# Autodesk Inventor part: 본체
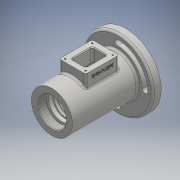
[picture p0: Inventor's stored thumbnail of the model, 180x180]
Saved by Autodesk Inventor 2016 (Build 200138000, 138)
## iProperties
Created: 2017-05
Part Number: 본체
Material: 일반
Document SubType Name: Modeling
Designer: USER
Density: 1 g/cm^3
Appearance: 기본값
Author: USER
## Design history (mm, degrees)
sketch "스케치1"
  geometry: C1 r 53 at (0, 0); 1 further point
  constraints: 1 centre point, 1 coincident
  dimensions: "d0" = 106 diameter of C1
extrude "돌출1" new body sketch "스케치1" distance "d1" = 13; taper "d2" = 0 deg
sketch "스케치2"
  geometry: C1 r 31 at (0, 0); 1 further point
  constraints: 1 centre point, 1 coincident
  dimensions: "d3" = 62 diameter of C1
extrude "돌출2" join sketch "스케치2" distance "d4" = 3; taper "d5" = 0 deg
sketch "스케치3"
  geometry: C1 r 31 at (0, 0); 1 further point
  constraints: 1 centre point, 1 coincident
  dimensions: "d6" = 62 diameter of C1
extrude "돌출3" join sketch "스케치3" distance "d7" = 99; taper "d8" = 0 deg
sketch "스케치4"
  geometry: L1 (-138.323, 0)-(35.373, 0); L2 (-99, 31)-(-99, -31) reference; L3 (-99, 0)-(-99, 21); L4 (-99, 21)-(-87, 21); L5 (-87, 21)-(-87, 24); L6 (-87, 24)-(-84, 24); L7 (-84, 24)-(-84, 20); L8 (-84, 20)-(-78, 20); L9 (-78, 20)-(-78, 17.5); L10 (-78, 17.5)-(-74.75, 17.5); L11 (-74.75, 17.5)-(-74.75, 18.5); L12 (-74.75, 18.5)-(-73, 18.5); L13 (-73, 18.5)-(-73, 17.5); L14 (-73, 17.5)-(-62, 17.5); L15 (-62, 17.5)-(-62, 26); L16 (-62, 26)-(-24, 26); L17 (-24, 26)-(-24, 17.5); L18 (-24, 17.5)-(-13, 17.5); L19 (-13, 17.5)-(-13, 16.5); L20 (-13, 16.5)-(-11, 16.5); L21 (-8, 13.5)-(-8, 10); L22 (-8, 10)-(-5.3, 10); L23 (-5.3, 10)-(-5.3, 12.5); L24 (-5.3, 12.5)-(2, 12.5); L25 (2, 12.5)-(2, 16); L26 (2, 16)-(16, 22); L27 (16, -31)-(16, 31) reference; L28 (0, 31)-(-99, 31) reference; L29 (16, 22)-(16, 0); L30 (-99, 0)-(16, 0); A1 r 3 centre (-11, 13.5) between (-8, 13.5) and (-11, 16.5); 1 further point
  constraints: 54 end point, 16 perpendicular, 4 horizontal, 3 vertical, 2 midpoint, 2 point on circle, 2 point on line, 2 tangent, 1 centre point, 1 collinear, 1 horizontal alignment
  dimensions: "d9" = 42 diameter of L4 L1; "d10" = 48 diameter of L6 L1; "d11" = 3 distance of L5.end L6.end; "d12" = 40 diameter of L8 L1; "d13" = 12 distance of L3.end L4.end; "d14" = 21 distance between parallel lines of L2 L9; "d15" = 35 diameter of L10 L1; "d16" = 37 diameter of L12 L1; "d17" = 1.75 distance of L11.end L12.end; "d18" = 26 distance between parallel lines of L3 L13; "d19" = 11 distance of L13.end L14.end; "d20" = 35 diameter of L14 L1; "d21" = 38 distance of L15.end L16.end; "d22" = 52 diameter of L16 L1; "d23" = 11 distance of L17.end L18.end; "d24" = 35 diameter of L18 L1; "d25" = 3 radius of A1; "d26" = 33 diameter of L20 L1; "d27" = 2.7 distance of L21.end L22.end; "d28" = 20 diameter of L22 L1; "d29" = 25 diameter of L24 L1; "d30" = 7.3 distance of L23.end L24.end; "d31" = 32 diameter of L25.end L1; "d32" = 44 diameter of L26.end L1; "d33" = 14 distance from line of L25 L26.end
revolve "회전1" sketch "스케치4" stored, may be unused: angle "d34" = 90 deg
fillet "모깎기2" dims "d36" = 0.3
chamfer "모따기1" distance "d37" = 1; stored, may be unused: second distance "d38" = 2, angle "d39" = 45 deg
fillet "모깎기3" dims "d43" = 0.3
chamfer "모따기4" distance "d47" = 0.7; stored, may be unused: second distance "d48" = 2, angle "d49" = 30 deg
fillet "모깎기4" dims "d50" = 3
sketch "스케치8"
  geometry: A1 r 41.5 centre (0, 0) between (0, 41.5) and (-41.5, 0); A2 r 45.5 centre (0, 0) between (0, 45.5) and (-45.5, 0); A3 r 37.5 centre (0, 0) between (0, 37.5) and (-37.5, 0); A4 r 4 centre (0, 41.5) between (0, 37.5) and (0, 45.5); A5 r 4 centre (-41.5, 0) between (-45.5, 0) and (-37.5, 0); A6 r 41.5 centre (0, 0) between (0, -41.5) and (41.5, 0); A7 r 45.5 centre (0, 0) between (0, -45.5) and (45.5, 0); A8 r 37.5 centre (0, 0) between (0, -37.5) and (37.5, 0); A9 r 4 centre (0, -41.5) between (0, -37.5) and (0, -45.5); A10 r 4 centre (41.5, 0) between (45.5, 0) and (37.5, 0); 1 further point
  constraints: 20 point on circle, 10 centre point, 8 tangent, 2 coincident, 2 horizontal alignment, 2 vertical alignment
  dimensions: "d51" = 45.5 radius of A2; "d53" = 41.5 radius of A1; "d54" = 45.5 radius of A7; "d55" = 41.5 radius of A6
extrude "돌출4" cut sketch "스케치8" stored distance "d56" = 99; taper "d57" = 0 deg
node "작업 평면1"
sketch "스케치9"
  geometry: L1 (-20, -18)-(20, -18); L2 (20, -18)-(20, -68); L3 (20, -68)-(-20, -68); L4 (-20, -68)-(-20, -18); L5 (-20, -43)-(0, -43); L6 (-31, -99)-(31, -99) reference; 2 further points
  constraints: 10 end point, 2 horizontal, 2 midpoint, 2 parallel, 1 perpendicular, 1 vertical alignment
  dimensions: "d59" = 50 distance of L1.end L2.end; "d60" = 40 distance of L1.start L1.end; "d61" = 56 distance between parallel lines of L6 L5
extrude "돌출5" join sketch "스케치9" stored distance "d62" = 99; taper "d63" = 0 deg
sketch "스케치10"
  geometry: L1 (-20, -18)-(20, -18) reference; L2 (-20, -68)-(-20, -18) reference; L3 (20, -68)-(-20, -68) reference; L4 (20, -18)-(20, -68) reference; L5 (-11, -27)-(11, -27); L6 (11, -27)-(11, -59); L7 (11, -59)-(-11, -59); L8 (-11, -59)-(-11, -27); 4 further points
  constraints: 8 end point, 3 midpoint, 2 parallel, 1 horizontal, 1 horizontal alignment, 1 perpendicular, 1 vertical alignment
  dimensions: "d64" = 32 distance of L5.end L6.end; "d65" = 22 distance of L6.end L7.end
extrude "돌출6" cut sketch "스케치10" stored distance "d66" = 99; taper "d67" = 0 deg
fillet "모깎기5" dims "d68" = 3
fillet "모깎기6" dims "d69" = 3
fillet "모깎기7" dims "d73" = 3
chamfer "모따기6" distance "d74" = 1; stored, may be unused: second distance "d75" = 2, angle "d76" = 30 deg
fillet "모깎기8" dims "d77" = 3
feature "스레드1" dims "d78" = 10, "d79" = 0
sketch "스케치11"
  geometry: L1 (-20, -65)-(-20, -21) reference; L2 (-20, -65)-(-20, -21) reference; L3 (-20, -43)-(20, -43); L4 (20, -21)-(20, -65) reference; L5 (17, -68)-(-17, -68) reference; L6 (0, -68)-(0, -18); L7 (17, -18)-(-17, -18) reference; 5 further points
  constraints: 4 end point, 4 midpoint, 2 horizontal alignment, 2 vertical alignment
  dimensions: "d80" = 41 distance of point (15.5, -63.5) point (15.5, -22.5); "d81" = 31 distance of point (15.5, -63.5) point (-15.5, -63.5); "d82" = 15.5 distance from line of point (-15.5, -63.5) L6; "d83" = 20.5 distance from line of point (-15.5, -22.5) L3
hole "구멍1" sketch "스케치11" at (-15.5, -22.5), (15.5, -22.5), (15.5, -63.5), (-15.5, -63.5) diameter "d84" = 2.459; stored, may be unused: countersink angle "d88" = 90 deg, drill point angle "d90" = 118 deg; dims "d85" = 6, "d86" = 4, "d87" = 2, "d89" = 8
sketch "스케치12"
  geometry: L1 (13, -34)-(75, -34) reference; L2 (0, 44)-(0, 0) reference; 2 further points
  constraints: 1 other
  dimensions: "d91" = 56 distance from line of L1 point (8, 22); "d92" = 8 distance from line of L2 point (8, 22)
feature "엠보싱1" sketch "스케치12" dims "d9" = 42, "d10" = 48, "d11" = 3, "d12" = 40, "d13" = 12, "d14" = 21, "d15" = 35, "d16" = 37, "d17" = 1.75, "d18" = 26, "d19" = 11, "d20" = 35, "d21" = 38, "d22" = 52, "d23" = 11, "d24" = 35, "d25" = 3, "d26" = 33, "d27" = 2.7, "d28" = 20, "d29" = 25, "d30" = 7.3, "d31" = 32, "d32" = 44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
node "솔리드1"
node "투영된 루프2"
other parameters: "d58" = 44
